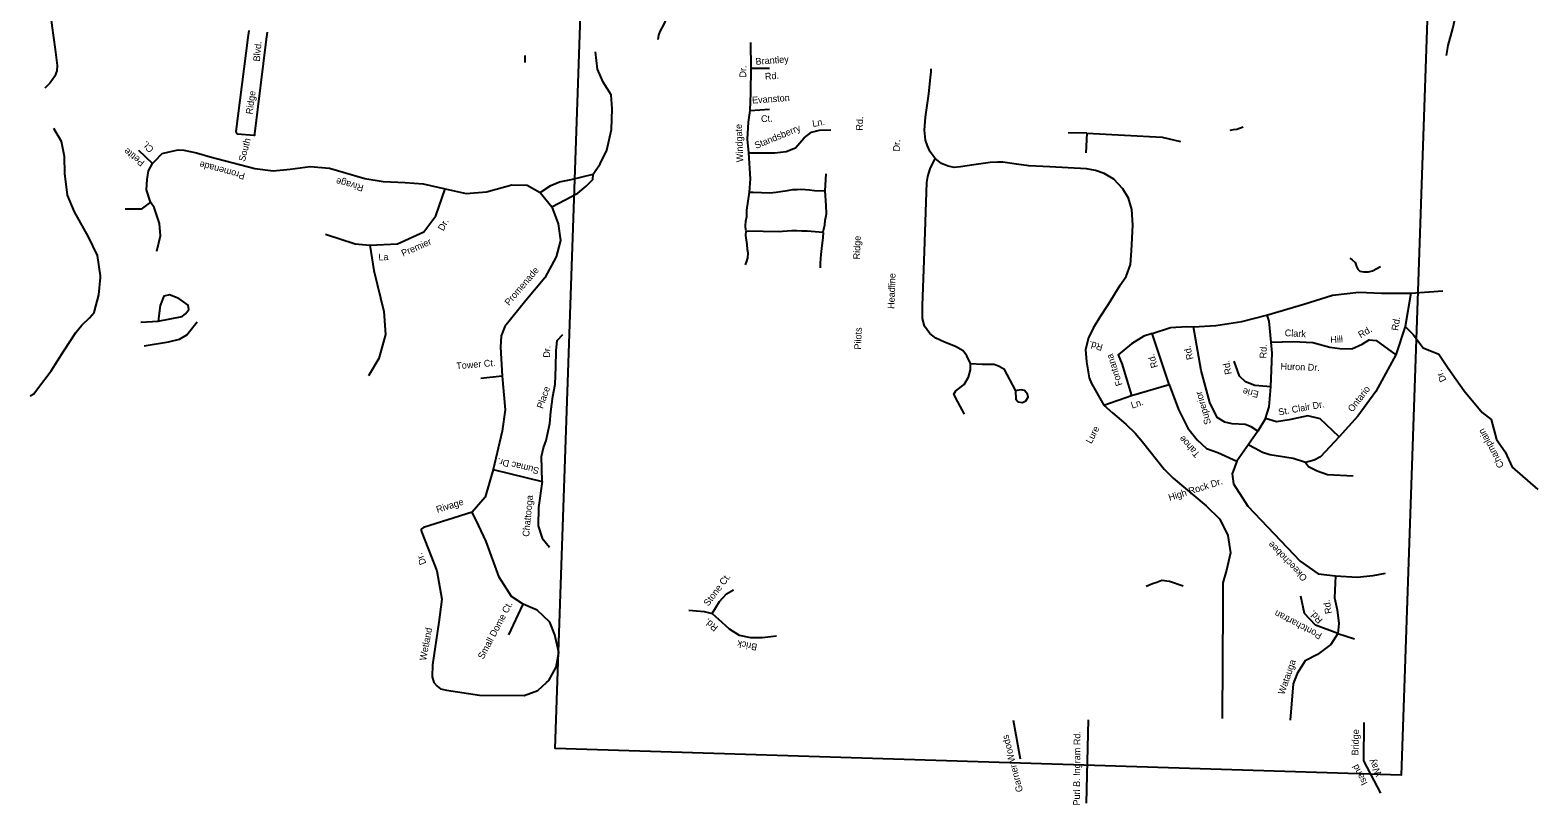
# Model space of a CAD drawing. Extents: x 2308163 to 2335412, y -96774 to 125428.
# Drawn here: x 2322030.2 to 2322144.4, y 82488 to 82546.6 of the extents above; entities that cross this region are included whole.
import ezdxf

# ---------------------------------------------------------------- set-up
doc = ezdxf.new("R2010")
doc.units = 0
for name, color, linetype in [('Old_Level_10', 7, 'Continuous'), ('Old_Level_35', 7, 'Continuous'), ('Old_Level_63', 7, 'Continuous')]:
    doc.layers.add(name, color=color, linetype=linetype)

msp = doc.modelspace()

# ---------------------------------------------------------------- linework, layer by layer
at = {"layer": 'Old_Level_35'}
for p, q in [((2322046.69, 82546.1), (2322046.76, 82546.62)), ((2322048.12, 82546.49), (2322048.05, 82545.96)), ((2322067.69, 82544.21), (2322067.67, 82544.73)), ((2322090.41, 82534.47), (2322090.5, 82535.77))]:
    msp.add_line(p, q, dxfattribs=at)
for points in [[(2322077.75, 82545.95), (2322077.8, 82546.27), (2322077.91, 82546.55), (2322078.23, 82547.15), (2322078.64, 82548.1), (2322079.24, 82549.62), (2322079.79, 82551.18), (2322080.67, 82553.3)], [(2322031.57, 82548.95), (2322031.6, 82548.7), (2322031.81, 82547.01), (2322032.07, 82545.18), (2322032.22, 82543.97), (2322032.2, 82543.56), (2322032.05, 82543.17), (2322031.68, 82542.65), (2322031.29, 82542.26)], [(2322137.51, 82544.73), (2322137.63, 82545.49), (2322137.99, 82546.78), (2322138.2, 82547.75), (2322138.25, 82548.22)], [(2322048.05, 82545.96), (2322047.18, 82538.79), (2322047.17, 82538.72), (2322047.17, 82538.7), (2322047.16, 82538.68), (2322047.14, 82538.67), (2322047.11, 82538.67), (2322045.89, 82538.77), (2322045.85, 82538.8), (2322045.82, 82538.84), (2322045.8, 82538.88), (2322045.8, 82538.92), (2322045.79, 82538.98), (2322046.69, 82546.1)], [(2322084.69, 82534.39), (2322084.76, 82535.39), (2322084.63, 82537.37), (2322084.54, 82538.4), (2322084.61, 82539.69), (2322084.74, 82540.57), (2322084.78, 82541.9), (2322084.82, 82543.77), (2322084.78, 82545.72)], [(2322069.69, 82533.27), (2322071.68, 82534.31), (2322072.3, 82534.84), (2322072.82, 82535.33), (2322072.84, 82535.73), (2322073.37, 82536.52), (2322073.86, 82537.57), (2322074.22, 82539.12), (2322074.27, 82540.68), (2322074.2, 82541.74), (2322073.58, 82542.72), (2322073.16, 82543.69), (2322073.02, 82545.01)], [(2322084.82, 82543.77), (2322086.19, 82543.77)], [(2322098.75, 82536.92), (2322098.37, 82537.44), (2322098.16, 82537.89), (2322098.02, 82538.32), (2322097.94, 82539.07), (2322098.02, 82540.06), (2322098.27, 82541.82), (2322098.4, 82543.07), (2322098.44, 82543.49), (2322098.46, 82543.72)], [(2322084.74, 82540.57), (2322086.2, 82540.67)], [(2322035.5, 82528.04), (2322035.28, 82529.59), (2322034.59, 82530.99), (2322033.54, 82532.88), (2322033, 82534.15), (2322032.79, 82535.79), (2322032.76, 82537.09), (2322032.54, 82538.21), (2322031.95, 82539.19)], [(2322084.63, 82537.37), (2322086.61, 82537.35), (2322087.47, 82537.47), (2322088.17, 82537.73), (2322088.83, 82538.49), (2322089.37, 82538.93), (2322089.99, 82539.08), (2322090.85, 82539.09)], [(2322110.25, 82538.84), (2322108.83, 82538.87)], [(2322110.25, 82538.84), (2322110.18, 82537.36)], [(2322110.25, 82538.84), (2322115.96, 82538.54), (2322117.35, 82538.21)], [(2322121.11, 82539.07), (2322121.37, 82539.12), (2322121.61, 82539.16), (2322121.82, 82539.23), (2322122.09, 82539.33)], [(2322039.45, 82536.55), (2322038.41, 82537.54)], [(2322039.28, 82533.63), (2322038.98, 82534.56), (2322039.04, 82535.34), (2322039.14, 82536), (2322039.45, 82536.55), (2322039.61, 82536.73), (2322040.18, 82537.3), (2322040.7, 82537.43), (2322041.38, 82537.59), (2322041.82, 82537.57), (2322042.78, 82537.36), (2322043.8, 82537.06)], [(2322043.8, 82537.06), (2322047.2, 82536.17), (2322048.58, 82536), (2322049.88, 82536.11), (2322051.39, 82536.33), (2322052.86, 82536.19), (2322055.52, 82535.42), (2322056.92, 82535.19), (2322058.58, 82535.1), (2322059.96, 82535.02), (2322061.61, 82534.63), (2322063.2, 82534.29), (2322064.74, 82534.4), (2322066.67, 82534.94), (2322067.84, 82534.9), (2322068.83, 82534.35), (2322069.69, 82533.27), (2322070.17, 82531.99), (2322070.37, 82530.73), (2322070.02, 82529.48), (2322069.16, 82527.88), (2322067.72, 82526.17), (2322066.14, 82524.2), (2322065.87, 82523.5), (2322065.81, 82522.64), (2322065.95, 82520.45), (2322066.17, 82517.89), (2322065.93, 82516.27), (2322065.25, 82513.37), (2322064.65, 82511.27), (2322063.66, 82510.13), (2322059.98, 82508.97), (2322059.8, 82508.85), (2322059.79, 82508.76), (2322059.85, 82508.6), (2322060.98, 82505.7), (2322061.37, 82503.54), (2322061.15, 82501.82), (2322060.67, 82498.58), (2322060.64, 82497.66), (2322060.75, 82497.25), (2322061.02, 82496.97), (2322061.26, 82496.77), (2322061.71, 82496.66), (2322064.22, 82496.27), (2322067.61, 82496.25), (2322068.64, 82496.64), (2322069.31, 82497.23), (2322069.47, 82497.38), (2322070.02, 82498.41), (2322070.22, 82499.51), (2322069.92, 82500.84), (2322069.56, 82501.81), (2322068.6, 82502.73), (2322067.54, 82503.17), (2322066.64, 82503.75), (2322065.7, 82505.23), (2322064.72, 82507.91), (2322064.17, 82509.1), (2322063.66, 82510.13)], [(2322101.42, 82521.39), (2322101.15, 82521.99), (2322100.88, 82522.36), (2322100.28, 82522.69), (2322099.45, 82523.01), (2322098.79, 82523.32), (2322098.34, 82523.68), (2322097.95, 82524.22), (2322097.78, 82524.82), (2322097.79, 82525.79), (2322097.94, 82529.89), (2322098.13, 82535.12), (2322098.19, 82535.56), (2322098.36, 82536.15), (2322098.75, 82536.92)], [(2322112.75, 82527.3), (2322113.22, 82527.99), (2322113.55, 82528.9), (2322113.64, 82529.93), (2322113.73, 82531.89), (2322113.65, 82533.07), (2322113.39, 82533.92), (2322112.98, 82534.63), (2322112.28, 82535.37), (2322111.57, 82535.79), (2322110.89, 82536.03), (2322110.21, 82536.15), (2322107.45, 82536.31), (2322105.86, 82536.38), (2322104.92, 82536.51), (2322103.89, 82536.66), (2322103.51, 82536.66), (2322102.92, 82536.62), (2322101.67, 82536.46), (2322100.67, 82536.29), (2322100.18, 82536.25), (2322099.74, 82536.34), (2322099.23, 82536.54), (2322098.75, 82536.92)], [(2322068.83, 82534.35), (2322069.63, 82534.89), (2322070.29, 82535.17), (2322071.16, 82535.34), (2322072.84, 82535.73)], [(2322052.55, 82531.21), (2322054.8, 82530.46), (2322055.91, 82530.36), (2322058, 82530.47), (2322060.01, 82531.38), (2322060.91, 82532.58), (2322061.61, 82534.63)], [(2322084.41, 82531.5), (2322084.39, 82531.84), (2322084.4, 82532.19), (2322084.48, 82532.54), (2322084.47, 82533.02), (2322084.69, 82534.39)], [(2322084.69, 82534.39), (2322084.95, 82534.38), (2322085.58, 82534.35), (2322086.22, 82534.33), (2322086.69, 82534.37), (2322087.04, 82534.42), (2322087.56, 82534.51), (2322087.97, 82534.57), (2322088.29, 82534.58), (2322088.55, 82534.6), (2322088.93, 82534.58), (2322089.23, 82534.56), (2322089.61, 82534.51), (2322090.41, 82534.47)], [(2322090.27, 82531.37), (2322090.4, 82531.91), (2322090.41, 82532.23), (2322090.51, 82532.74), (2322090.48, 82533.37), (2322090.41, 82534.47)], [(2322039.78, 82529.91), (2322040.04, 82531.08), (2322039.96, 82532.01), (2322039.56, 82533.21), (2322039.28, 82533.63), (2322038.59, 82533.09), (2322037.37, 82533.1)], [(2322084.37, 82528.87), (2322084.48, 82529.16), (2322084.55, 82529.4), (2322084.59, 82529.77), (2322084.52, 82530.04), (2322084.5, 82530.42), (2322084.41, 82531.09), (2322084.44, 82531.45)], [(2322084.46, 82531.46), (2322086.99, 82531.41), (2322087.17, 82531.43), (2322087.9, 82531.48), (2322088.27, 82531.48), (2322088.65, 82531.45), (2322089.04, 82531.45), (2322090.27, 82531.36)], [(2322055.91, 82530.36), (2322056.21, 82528.44), (2322056.97, 82525.34), (2322057.09, 82523.61), (2322056.6, 82521.78), (2322055.81, 82520.46)], [(2322090.05, 82528.64), (2322090.07, 82529), (2322090.08, 82529.36), (2322090.1, 82529.65), (2322090.17, 82530.1), (2322090.27, 82530.95), (2322090.3, 82531.33)], [(2322130.18, 82529.39), (2322130.34, 82529.26), (2322130.57, 82529.04), (2322130.69, 82528.75), (2322130.77, 82528.54), (2322130.93, 82528.4), (2322131.23, 82528.34), (2322131.58, 82528.34), (2322131.9, 82528.43), (2322132.49, 82528.76)], [(2322030.17, 82518.96), (2322030.45, 82519.11), (2322030.73, 82519.49), (2322031.75, 82520.85), (2322032.71, 82522.37), (2322033.63, 82523.75), (2322034.08, 82524.3), (2322034.67, 82524.85), (2322035.01, 82525.27), (2322035.38, 82526.6), (2322035.5, 82527.91), (2322035.5, 82528.04)], [(2322112.75, 82527.3), (2322111.86, 82525.86), (2322111.23, 82524.92), (2322110.73, 82524.07), (2322110.37, 82523.34), (2322110.15, 82522.47), (2322110.21, 82521.52), (2322110.42, 82520.32), (2322110.6, 82519.88), (2322111.54, 82518.24), (2322112.18, 82517.66), (2322113.19, 82516.81), (2322113.92, 82516.12), (2322114.46, 82515.48), (2322116.1, 82513.41), (2322116.78, 82512.72), (2322119.3, 82510.63), (2322120.32, 82509.61), (2322120.94, 82508.38), (2322121.14, 82507.07), (2322120.82, 82505.75), (2322120.55, 82504.78), (2322120.56, 82503.01), (2322120.5, 82494.52)], [(2322134.8, 82526.72), (2322137.22, 82526.9)], [(2322038.55, 82524.53), (2322039.87, 82524.61), (2322041.69, 82524.95), (2322041.96, 82525.18), (2322042.19, 82525.49), (2322042.15, 82525.81), (2322041.43, 82526.32), (2322040.73, 82526.61), (2322040.31, 82526.5), (2322040.02, 82525.8)], [(2322040.02, 82525.8), (2322039.87, 82524.61)], [(2322115.19, 82523.68), (2322116.58, 82524.14), (2322117.83, 82524.21), (2322118.32, 82524.18), (2322120.03, 82524.28), (2322121.99, 82524.59), (2322123.87, 82525.05), (2322126.7, 82525.89), (2322128.87, 82526.59), (2322130.86, 82526.8), (2322132.57, 82526.74), (2322134.8, 82526.72)], [(2322134.8, 82526.72), (2322134.37, 82524.21), (2322133.66, 82522.05), (2322132.14, 82519.27), (2322130.77, 82517.42), (2322129.36, 82515.84), (2322127.95, 82514.32), (2322127.48, 82514.07), (2322126.81, 82513.9), (2322125.88, 82514.2), (2322124.12, 82514.48), (2322123.56, 82514.65), (2322122.99, 82514.96), (2322122.48, 82515.24)], [(2322038.81, 82522.74), (2322040.66, 82523.05), (2322041.49, 82523.24), (2322042.04, 82523.58), (2322042.83, 82524.56)], [(2322124.22, 82523.01), (2322124.06, 82524.62), (2322123.92, 82525.07)], [(2322068.98, 82512.46), (2322068.92, 82514.36), (2322069.07, 82515.02), (2322069.26, 82515.56), (2322069.56, 82516.86), (2322069.63, 82517.74), (2322069.79, 82518.91), (2322069.95, 82519.83), (2322070, 82521.13), (2322070.04, 82522.35), (2322070.11, 82523.15), (2322070.54, 82523.59)], [(2322116.49, 82519.82), (2322115.19, 82523.68), (2322114.56, 82523.47), (2322113.62, 82522.88), (2322112.63, 82522.07), (2322112.92, 82521.33), (2322113.2, 82520.38), (2322113.62, 82518.99)], [(2322123.21, 82516.27), (2322122.71, 82516.61), (2322122.25, 82516.77), (2322121.27, 82516.83), (2322120.7, 82516.95), (2322120.13, 82517.3), (2322119.56, 82518.46), (2322118.9, 82520.88), (2322118.32, 82524.18)], [(2322134.37, 82524.21), (2322134.97, 82523.59), (2322135.74, 82522.59), (2322136.92, 82522.1), (2322137.63, 82521.04), (2322138.83, 82519.34), (2322140.21, 82517.69), (2322140.88, 82517.15), (2322141.29, 82515.64), (2322141.94, 82514.71), (2322142.48, 82513.54), (2322144.42, 82511.87)], [(2322129.36, 82515.84), (2322127.94, 82517.22), (2322127, 82517.43), (2322125.57, 82517.14), (2322124.61, 82516.99), (2322123.79, 82517.23), (2322124.05, 82518.11), (2322124.18, 82519.63), (2322124.28, 82522.19), (2322124.22, 82523.01)], [(2322124.22, 82523.01), (2322125.88, 82523.07), (2322127.38, 82522.98), (2322128.66, 82522.63), (2322129.42, 82522.54), (2322130.32, 82522.52), (2322131.11, 82522.87), (2322131.63, 82523.19), (2322132.17, 82523.15), (2322133.66, 82522.05)], [(2322100.97, 82517.57), (2322100.47, 82518.5), (2322100.17, 82519.08), (2322100.31, 82519.32), (2322100.95, 82519.8), (2322101.29, 82520.36), (2322101.43, 82520.92), (2322101.42, 82521.39)], [(2322101.42, 82521.39), (2322102.32, 82521.36), (2322103.22, 82521.34), (2322103.61, 82521.21), (2322103.95, 82521), (2322104.83, 82519.33), (2322104.86, 82518.7), (2322105.04, 82518.51), (2322105.36, 82518.44), (2322105.63, 82518.58), (2322105.81, 82518.85), (2322105.75, 82519.09), (2322105.51, 82519.36), (2322105.27, 82519.41), (2322104.95, 82519.36), (2322104.83, 82519.33)], [(2322124.18, 82519.63), (2322122.98, 82519.73), (2322122.27, 82520.02), (2322121.82, 82520.45), (2322121.42, 82521.57)], [(2322064.33, 82520.3), (2322065.95, 82520.48)], [(2322111.54, 82518.24), (2322113.62, 82518.99)], [(2322113.62, 82518.99), (2322116.49, 82519.82)], [(2322116.49, 82519.82), (2322117.19, 82517.91), (2322117.89, 82516.51), (2322118.6, 82515.63), (2322119.32, 82514.97), (2322120.17, 82514.65), (2322121.6, 82514)], [(2322123.79, 82517.23), (2322123.21, 82516.27), (2322121.6, 82514), (2322121.26, 82513.04), (2322121.35, 82512.29), (2322122.44, 82510.59), (2322126.42, 82506.44), (2322127.77, 82505.48), (2322129.08, 82505.32), (2322130.74, 82505.21), (2322131.94, 82505.34), (2322132.87, 82505.53)], [(2322065.25, 82513.37), (2322068.98, 82512.46), (2322068.7, 82510.5), (2322068.66, 82509.11), (2322068.96, 82508.18), (2322069.53, 82507.48)], [(2322126.81, 82513.9), (2322127.04, 82513.61), (2322127.69, 82513.27), (2322128.49, 82512.99), (2322130.43, 82512.89)], [(2322129.08, 82505.32), (2322129.02, 82503.66), (2322129.22, 82502.74), (2322129.35, 82501.7), (2322129.27, 82500.96), (2322128.73, 82500.12), (2322127.73, 82499.35), (2322126.79, 82498.87), (2322126.19, 82497.92), (2322125.87, 82497.13), (2322125.66, 82494.38)], [(2322081.85, 82502.47), (2322082.4, 82503.38), (2322082.95, 82503.96), (2322083.48, 82504.26)], [(2322114.73, 82504.53), (2322115.23, 82504.75), (2322115.55, 82504.85), (2322115.93, 82504.98), (2322116.51, 82504.91), (2322117.54, 82504.55)], [(2322066.44, 82500.86), (2322067.54, 82503.17)], [(2322129.27, 82500.96), (2322127.57, 82501.57), (2322126.74, 82502.46), (2322126.45, 82503.79)], [(2322080.09, 82502.73), (2322081.25, 82502.61), (2322081.85, 82502.47), (2322082.59, 82501.8), (2322083.14, 82501.3), (2322083.89, 82500.83), (2322084.76, 82500.64), (2322085.65, 82500.65), (2322086.73, 82500.78)], [(2322129.27, 82500.96), (2322130.52, 82500.55)], [(2322105.23, 82491.44), (2322104.7, 82494.36)], [(2322110.21, 82488.11), (2322110.37, 82494.4)], [(2322132.52, 82488.86), (2322131.23, 82491.31), (2322131.27, 82494.2)]]:
    msp.add_lwpolyline(points, dxfattribs=at)
at = {"layer": 'Old_Level_63'}
msp.add_lwpolyline([(2322137.61, 82592.9), (2322134.07, 82490.21), (2322069.96, 82492.24), (2322074.1, 82612.06)], dxfattribs=at)

# ---------------------------------------------------------------- texts
at = {"layer": 'Old_Level_10'}
for s, height, rotation, p in [('Blvd.', 0.513, 85.2272, (2322047.58, 82544.26)), ('Brantley', 0.513, 4.3646, (2322085.16, 82544.02)), ('Dr.', 0.513, 89.4385, (2322084.43, 82543.06)), ('Rd.', 0.513, 4.3646, (2322085.87, 82542.89)), ('Ridge', 0.513, 81.8623, (2322047.01, 82540.25)), ('Evanston', 0.513, 3.9715, (2322084.89, 82541.09)), ('Windgate', 0.513, 92.2238, (2322084.21, 82536.66)), ('Standsberry', 0.5126, 22.4236, (2322085.19, 82537.65)), ('Ct.', 0.513, 3.9715, (2322085.57, 82539.67)), ('Ln.', 0.513, 10.8306, (2322089.49, 82539.31)), ('Rd.', 0.513, 87.9298, (2322093.26, 82539.03)), ('South ', 0.513, 75.4775, (2322046.44, 82536.66)), ('Dr.', 0.513, 87.0673, (2322096.06, 82537.45)), ('Petite', 0.513, 141.9823, (2322038.89, 82536.69)), ('Ct.', 0.513, 134.3578, (2322039.58, 82537.67)), ('Promenade', 0.513, 164.8185, (2322046.49, 82535.81)), ('Rivage ', 0.513, 164.9249, (2322055.48, 82534.91)), ('Dr.', 0.513, 61.5716, (2322061.48, 82531.4)), ('Premier ', 0.513, 23.573, (2322058.43, 82529.49)), ('Ridge', 0.513, 88.0247, (2322093.05, 82529.28)), ('La ', 0.513, 2.8628, (2322056.57, 82529.2)), ('Promenade', 0.513, 49.5056, (2322066.46, 82525.75)), ('Headline', 0.513, 88.0247, (2322095.66, 82525.53)), ('Rd.', 0.513, 80.9562, (2322133.83, 82523.86)), ('Pilots', 0.513, 87.8633, (2322093.13, 82522.45)), ('Clark', 0.513, 356.6269, (2322125.23, 82523.48)), ('Hill', 0.513, 3.1309, (2322128.71, 82522.95)), ('Rd.', 0.513, 29.8603, (2322130.99, 82523.31)), ('Dr.', 0.513, 87.4369, (2322069.55, 82521.83)), ('Rd.', 0.513, 164.5659, (2322111.5, 82522.84)), ('Rd.', 0.513, 103.6352, (2322118.33, 82521.75)), ('Rd.', 0.513, 87.8778, (2322123.85, 82521.78)), ('Tower Ct.', 0.513, 4.9538, (2322062.48, 82520.96)), ('Fontana', 0.513, 107.7984, (2322112.96, 82519.79)), ('Rd.', 0.513, 106.6838, (2322115.64, 82521.15)), ('Rd.', 0.513, 101.3226, (2322121.23, 82520.62)), ('Huron Dr.', 0.513, 358.0247, (2322124.92, 82520.94)), ('Dr.', 0.513, 116.2723, (2322137.51, 82520.15)), ('Place', 0.513, 71.0915, (2322069.02, 82517.94)), ('Superior', 0.513, 106.4077, (2322119.67, 82516.86)), ('Erie', 0.513, 167.3506, (2322123.31, 82519.29)), ('Ontario', 0.513, 52.5914, (2322130.38, 82517.68)), ('Ln.', 0.513, 18.5093, (2322113.68, 82517.98)), ('St. Clair Dr.', 0.5126, 10.3937, (2322124.81, 82517.46)), ('Lure', 0.513, 62.5274, (2322110.59, 82515.28)), ('Tahoe', 0.513, 132.3947, (2322118.86, 82514.56)), ('Champlain', 0.513, 118.4032, (2322141.88, 82513.65)), ('Sumac Dr.', 0.513, 166.5432, (2322068.78, 82513.5)), ('High Rock Dr.', 0.5126, 17.5209, (2322116.52, 82510.99)), ('Rivage ', 0.513, 17.4763, (2322061.03, 82510.08)), ('Chattooga', 0.513, 84.5243, (2322067.98, 82508.26)), ('Okeechobee', 0.513, 134.2898, (2322126.99, 82505.2)), ('Dr.', 0.513, 112.2366, (2322060.2, 82506.27)), ('Stone Ct.', 0.513, 52.9539, (2322081.56, 82502.98)), ('Small Dome Ct.', 0.5126, 62.207, (2322064.51, 82498.96)), ('Rd.', 0.513, 99.3895, (2322128.82, 82502.48)), ('Rd.', 0.513, 140.7679, (2322082.35, 82501.46)), ('Pontchartran', 0.5126, 152.5317, (2322128.11, 82500.93)), ('Rd.', 0.513, 134.4566, (2322128.16, 82502)), ('Wetland', 0.513, 79.2672, (2322060.17, 82498.87)), ('Brick', 0.513, 169.0975, (2322085.3, 82500.15)), ('Watauga', 0.513, 70.8529, (2322125.2, 82496.28)), ('Garner Woods', 0.5126, 104.4911, (2322105.41, 82489.01)), ('Purl B. Ingram Rd.', 0.5126, 89.5734, (2322109.72, 82487.92)), ('Bridge', 0.513, 88.4171, (2322130.82, 82491.71)), ('Isand', 0.513, 117.301, (2322131.54, 82489.61)), ('Way', 0.513, 117.301, (2322132.63, 82490.29))]:
    msp.add_text(s, height=height, rotation=rotation, dxfattribs=at).set_placement(p)

doc.saveas('drawing.dxf')
